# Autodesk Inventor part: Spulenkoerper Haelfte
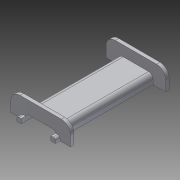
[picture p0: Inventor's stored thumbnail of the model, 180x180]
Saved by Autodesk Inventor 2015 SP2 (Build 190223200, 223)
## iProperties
Created: 2015-10
Part Number: Spulenkoerper Haelfte
Material: PC/ABS-Kunststoff
Document SubType Name: Modeling
Designer: rYan
Mass: 0.345661 g
Surface Area: 21.13 cm^2
Volume: 0.9675 cm^3
Density: 0.357273 g/cm^3
Appearance: Glatt - weiß
Author: rYan
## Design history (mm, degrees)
sketch "Skizze1"
  geometry: L1 (-10.5, 0)-(10.5, 0) reference; L2 (0, -0.8)-(0, 4.8) reference; L3 (6.5, 3)-(-6.5, 3); L4 (-6.5, 3)-(-6.5, 0); L5 (6.5, 3)-(6.5, 0); L6 (-6.5, 0)-(-7.5, 0); L7 (-7.5, 0)-(-7.5, 4); L8 (-7.5, 4)-(7.5, 4); L9 (7.5, 4)-(7.5, 0); L10 (7.5, 0)-(6.5, 0); 1 further point
  constraints: 17 end point, 4 perpendicular, 3 point on line, 2 horizontal, 1 parallel, 2 other
  dimensions: "d0" = 13 distance of L3.start L3.end; "d1" = 3 distance between parallel lines of L1 L3; "d2" = 1 distance between parallel lines of L8 L3; "d3" = 1 distance between parallel lines of L4 L7
extrude "Extrusion1" new body sketch "Skizze1" stored distance "d6" = 40; taper "d7" = 0 deg
sketch "Skizze2"
  geometry: L1 (-13, 8.5)-(13, 8.5); L2 (13, 8.5)-(13, 0); L3 (13, 0)-(6.5, 0); L4 (6.5, 0)-(6.5, 3); L5 (6.5, 3)-(-6.5, 3); L6 (-6.5, 3)-(-6.5, 0); L7 (-6.5, 0)-(-13, 0); L8 (-13, 0)-(-13, 8.5); L9 (0, 10.2)-(0, -1.7) reference; L10 (-18.2, 0)-(18.2, 0) reference; L11 (-6.5, 0)-(-6.5, 3) reference; L12 (-6.5, 3)-(6.5, 3) reference; 1 further point
  constraints: 16 end point, 6 perpendicular, 3 collinear, 2 point on line, 1 horizontal, 2 other
  dimensions: "d10" = 26 distance of L1.start L1.end; "d11" = 8.5 distance between parallel lines of L10 L1
extrude "Extrusion2" join sketch "Skizze2" distance "d13" = 1.5; taper "d14" = 0 deg
sketch "Skizze3"
  geometry: L1 (8.45, 1.95)-(8.45, 0); L2 (8.45, 0)-(6.5, 0); L3 (6.5, 0)-(6.5, 1.95); L4 (0, 10.2)-(0, -1.7) reference; L5 (-6.5, 0)-(-6.5, 3) reference; L6 (-6.5, 3)-(6.5, 3) reference; L7 (-18.2, 0)-(18.2, 0) reference; L8 (6.5, 1.95)-(8.45, 1.95); L9 (6.5, 3)-(6.5, 0) reference; L10 (-6.5, 0)-(-8.45, 0); L11 (-8.45, 0)-(-8.45, 1.95); L12 (-8.45, 1.95)-(-6.5, 1.95); L13 (-6.5, 1.95)-(-6.5, 0); 1 further point
  constraints: 16 end point, 3 perpendicular, 2 horizontal, 2 parallel, 1 collinear, 2 other
  dimensions: "d36" = 1.95 distance of L11.end L12.end; "d37" = 1.95 distance of L10.end L11.end
extrude "Extrusion3" join sketch "Skizze3" distance "d17" = 2; taper "d18" = 0 deg
mirror "Spiegeln1"
fillet "Rundung2" dims "d31" = 2
fillet "Rundung6" dims "d40" = 1
fillet "Rundung7" dims "d41" = 1
fillet "Rundung8" dims "d42" = 4
node "Volumenkörper1"
